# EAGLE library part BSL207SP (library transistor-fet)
OptiMOS(R)-P Small-Signal-Transistor P-Channel, Enhancement mode, Super Logic Level (2.5 V rated) Source: http://www.infineon.com/upload/Document/BSL207SP_Rev2.01.pdf
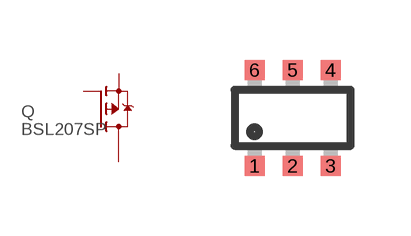
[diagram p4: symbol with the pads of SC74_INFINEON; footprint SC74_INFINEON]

Designator prefix Q

## BSL207SP  [SC74_INFINEON]
1  D  pas
2  D  pas
3  G  pas
4  S  pas
5  D  pas
6  D  pas

## Footprint SC74_INFINEON (pad centres in mm)
Small Outline Transistor; 6 leads Reflow soldering INFINEON, www.infineon.com/cmc_upload/0/000/010/257/eh_db_5b.pdf
smd 0.5 x 0.5: 1 -0.95,-1.2; 2 0,-1.2; 3 0.95,-1.2; 4 0.95,1.2; 5 0,1.2; 6 -0.95,1.2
